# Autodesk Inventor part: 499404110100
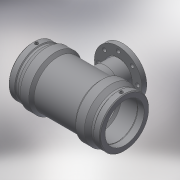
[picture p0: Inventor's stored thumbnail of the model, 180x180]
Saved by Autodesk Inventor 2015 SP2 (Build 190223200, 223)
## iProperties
Created: 2017-06
Part Number: 499404110100
Material: Generic
Description: PLASSON FLANGED TEE 110x100x110
Document SubType Name: Modeling
Designer: KIM
Mass: 57.3761 g
Surface Area: 241.06 cm^2
Volume: 57.3761 cm^3
Density: 1 g/cm^3
Appearance: Default
Author: KIM
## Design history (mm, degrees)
derived "499404.ipt"
feature "Solid1::499404.ipt"
tag "TaggingFeature1"
body "Solid1"
other parameters: "d13" = 326, "d14" = 17.6296, "d17" = 99, "d19" = 3.52592, "d20" = 168 deg, "d22" = 132.99, "d23" = 143, "d24" = 129.0003, "d25" = 135 deg, "d26" = 228.2, "d27" = 135 deg, "d29" = 81, "d35" = 15, "d39" = 5 deg, "d45" = 4, "d46" = 14, "d47" = 0, "d48" = -181, "d55" = 128.7, "d56" = 143, "d57" = 114.1, "d58" = 135 deg, "d59" = 71, "d60" = 71, "d61" = 135 deg, "d62" = 181, "d72" = 148.33, "d73" = 74.165, "d74" = -181, "d84" = 181, "d87" = 158, "d90" = 125, "d91" = 15 deg, "d93" = 22, "d95" = 4.74, "d97" = 18, "d100" = 0, "d102" = 360 deg, "d105" = 0, "d107" = 0, "d108" = 3, "d109" = 0, "d110" = 21.3, "d111" = 7.1, "L_" = 326, "L_1" = 71, "D_" = 143, "A_" = 81, "d_2" = 12, "H_" = 181, "t_" = 22, "d_1" = 158, "s_" = 18
